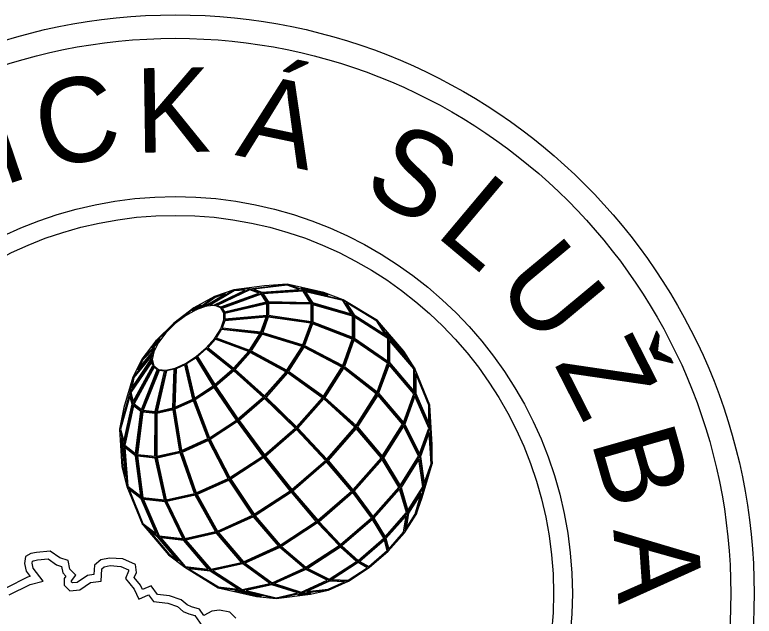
# Model space of a CAD drawing. Extents: x -820854 to -820609, y -1070840 to -1070004.
# Drawn here: x -820678.53 to -820668.06, y -1070178.74 to -1070170.22 of the extents above; entities that cross this region are included whole.
import ezdxf

# ---------------------------------------------------------------- set-up
doc = ezdxf.new("R2010")
doc.units = 0
doc.layers.add('Vrstva 63', color=7, linetype='Continuous')

msp = doc.modelspace()

# ---------------------------------------------------------------- linework, layer by layer
at = {"layer": 'Vrstva 63'}
for p, q in [((-820675.957, -1070174.397), (-820675.698, -1070174.211)), ((-820675.815, -1070174.348), (-820675.426, -1070174.117)), ((-820676.109, -1070174.481), (-820675.99, -1070174.372)), ((-820676.257, -1070174.593), (-820676.275, -1070174.587)), ((-820676.389, -1070174.723), (-820676.528, -1070174.837)), ((-820676.493, -1070174.86), (-820676.727, -1070175.099)), ((-820676.559, -1070174.991), (-820676.854, -1070175.351)), ((-820672.629, -1070176.309), (-820672.664, -1070175.749))]:
    msp.add_line(p, q, dxfattribs=at)
for points in [[(-820676.528, -1070174.837), (-820676.727, -1070175.099), (-820676.854, -1070175.351), (-820676.984, -1070175.784), (-820677.045, -1070176.089), (-820677.013, -1070176.624), (-820676.94, -1070176.902), (-820676.723, -1070177.432), (-820676.353, -1070177.867), (-820676.121, -1070178.046), (-820675.646, -1070178.336), (-820675.104, -1070178.459), (-820674.826, -1070178.49), (-820674.34, -1070178.425), (-820674.087, -1070178.369), (-820673.802, -1070178.24), (-820673.51, -1070178.05), (-820673.238, -1070177.815), (-820673.01, -1070177.556), (-820672.845, -1070177.296), (-820672.759, -1070177.059), (-820672.615, -1070176.58), (-820672.615, -1070176.309), (-820672.651, -1070175.748), (-820672.862, -1070175.23), (-820673.02, -1070174.986), (-820673.39, -1070174.551), (-820673.876, -1070174.255), (-820674.153, -1070174.152), (-820674.669, -1070174.036), (-820674.989, -1070174.06), (-820675.426, -1070174.117), (-820675.698, -1070174.211), (-820675.99, -1070174.372), (-820676.275, -1070174.587)], [(-820675.141, -1070174.107), (-820675.031, -1070174.147), (-820674.502, -1070174.112), (-820674.671, -1070174.05)], [(-820674.475, -1070174.093), (-820674.435, -1070174.108), (-820674.088, -1070174.191), (-820674.157, -1070174.165)], [(-820675.876, -1070174.355), (-820675.82, -1070174.336), (-820675.544, -1070174.172), (-820675.692, -1070174.223)], [(-820675.759, -1070174.331), (-820675.699, -1070174.326), (-820675.267, -1070174.119), (-820675.422, -1070174.13)], [(-820675.197, -1070174.114), (-820675.662, -1070174.337), (-820675.61, -1070174.357), (-820675.072, -1070174.161)], [(-820675.59, -1070174.377), (-820675.559, -1070174.425), (-820674.968, -1070174.285), (-820675.038, -1070174.177)], [(-820675.01, -1070174.172), (-820674.94, -1070174.281), (-820674.343, -1070174.293), (-820674.446, -1070174.135)], [(-820674.41, -1070174.142), (-820674.31, -1070174.296), (-820673.762, -1070174.456), (-820673.884, -1070174.266)], [(-820674.96, -1070174.311), (-820675.552, -1070174.451), (-820675.552, -1070174.527), (-820674.96, -1070174.476)], [(-820674.934, -1070174.308), (-820674.934, -1070174.476), (-820674.332, -1070174.563), (-820674.332, -1070174.32)], [(-820673.833, -1070174.296), (-820673.722, -1070174.469), (-820673.276, -1070174.751), (-820673.399, -1070174.561)], [(-820676.109, -1070175.157), (-820675.957, -1070175.058), (-820675.815, -1070174.935), (-820675.696, -1070174.8), (-820675.61, -1070174.665), (-820675.565, -1070174.541), (-820675.565, -1070174.44), (-820675.61, -1070174.371), (-820675.696, -1070174.339), (-820675.815, -1070174.348), (-820675.957, -1070174.397), (-820676.109, -1070174.481), (-820676.257, -1070174.593), (-820676.389, -1070174.723), (-820676.493, -1070174.86), (-820676.559, -1070174.991), (-820676.581, -1070175.104), (-820676.559, -1070175.191), (-820676.493, -1070175.242), (-820676.389, -1070175.253), (-820676.257, -1070175.224)], [(-820675.982, -1070174.383), (-820676.017, -1070174.415), (-820675.964, -1070174.386), (-820675.888, -1070174.331)], [(-820674.305, -1070174.325), (-820674.305, -1070174.569), (-820673.744, -1070174.786), (-820673.744, -1070174.489)], [(-820674.966, -1070174.503), (-820675.555, -1070174.554), (-820675.592, -1070174.653), (-820675.042, -1070174.711)], [(-820674.337, -1070174.589), (-820674.938, -1070174.502), (-820675.016, -1070174.717), (-820674.447, -1070174.893)], [(-820673.718, -1070174.503), (-820673.718, -1070174.798), (-820673.245, -1070175.124), (-820673.245, -1070174.802)], [(-820676.288, -1070174.619), (-820676.313, -1070174.644)], [(-820676.258, -1070174.592), (-820676.246, -1070174.583)], [(-820673.748, -1070174.813), (-820674.311, -1070174.595), (-820674.423, -1070174.903), (-820673.883, -1070175.185)], [(-820675.056, -1070174.736), (-820675.603, -1070174.679), (-820675.676, -1070174.793), (-820675.203, -1070174.969)], [(-820673.269, -1070174.714), (-820673.221, -1070174.787), (-820672.983, -1070175.067), (-820673.03, -1070174.994)], [(-820676.589, -1070174.939), (-820676.503, -1070174.851), (-820676.468, -1070174.805), (-820676.518, -1070174.847)], [(-820675.22, -1070174.99), (-820675.692, -1070174.816), (-820675.796, -1070174.933), (-820675.428, -1070175.225)], [(-820674.46, -1070174.917), (-820675.027, -1070174.741), (-820675.179, -1070174.98), (-820674.674, -1070175.255)], [(-820673.248, -1070175.155), (-820673.725, -1070174.826), (-820673.86, -1070175.2), (-820673.396, -1070175.562)], [(-820673.219, -1070174.831), (-820673.219, -1070175.145), (-820672.875, -1070175.549), (-820672.875, -1070175.235)], [(-820676.788, -1070175.249), (-820676.57, -1070174.984), (-820676.543, -1070174.931), (-820676.716, -1070175.107)], [(-820673.895, -1070175.209), (-820674.434, -1070174.927), (-820674.651, -1070175.269), (-820674.157, -1070175.622)], [(-820676.872, -1070175.507), (-820676.594, -1070175.099), (-820676.582, -1070175.04), (-820676.841, -1070175.357)], [(-820675.447, -1070175.244), (-820675.815, -1070174.952), (-820675.939, -1070175.06), (-820675.695, -1070175.458)], [(-820674.69, -1070175.276), (-820675.195, -1070175.001), (-820675.408, -1070175.242), (-820674.99, -1070175.616)], [(-820676.85, -1070175.698), (-820676.573, -1070175.189), (-820676.587, -1070175.136), (-820676.883, -1070175.571)], [(-820675.961, -1070175.076), (-820676.094, -1070175.163), (-820675.981, -1070175.648), (-820675.716, -1070175.475)], [(-820676.733, -1070175.811), (-820676.509, -1070175.246), (-820676.555, -1070175.211), (-820676.837, -1070175.731)], [(-820676.405, -1070175.265), (-820676.484, -1070175.256), (-820676.708, -1070175.821), (-820676.538, -1070175.84)], [(-820676.288, -1070175.788), (-820676.271, -1070175.241), (-820676.378, -1070175.264), (-820676.51, -1070175.837)], [(-820676.118, -1070175.176), (-820676.244, -1070175.233), (-820676.261, -1070175.777), (-820676.005, -1070175.662)], [(-820673.873, -1070175.224), (-820674.136, -1070175.639), (-820673.694, -1070176.039), (-820673.408, -1070175.587)], [(-820673.227, -1070175.176), (-820673.375, -1070175.581), (-820673.024, -1070175.993), (-820672.877, -1070175.587)], [(-820675.009, -1070175.635), (-820675.426, -1070175.261), (-820675.681, -1070175.481), (-820675.367, -1070175.944)], [(-820674.173, -1070175.643), (-820674.667, -1070175.291), (-820674.97, -1070175.634), (-820674.538, -1070176.057)], [(-820672.849, -1070175.298), (-820672.849, -1070175.582), (-820672.664, -1070176.01), (-820672.664, -1070175.751)], [(-820675.388, -1070175.96), (-820675.702, -1070175.497), (-820675.974, -1070175.675), (-820675.77, -1070176.21)], [(-820676.985, -1070176.264), (-820676.867, -1070175.734), (-820676.898, -1070175.619), (-820677.031, -1070176.089)], [(-820674.557, -1070176.076), (-820674.989, -1070175.653), (-820675.351, -1070175.965), (-820674.993, -1070176.453)], [(-820674.152, -1070175.66), (-820674.52, -1070176.076), (-820674.11, -1070176.514), (-820673.71, -1070176.061)], [(-820673.388, -1070175.607), (-820673.675, -1070176.058), (-820673.323, -1070176.472), (-820673.036, -1070176.02)], [(-820672.665, -1070176.075), (-820672.861, -1070175.621), (-820673.005, -1070176.018), (-820672.798, -1070176.44)], [(-820676.817, -1070176.433), (-820676.741, -1070175.838), (-820676.845, -1070175.757), (-820676.97, -1070176.315)], [(-820675.794, -1070176.223), (-820675.997, -1070175.687), (-820676.26, -1070175.806), (-820676.165, -1070176.391)], [(-820676.542, -1070176.473), (-820676.541, -1070175.866), (-820676.715, -1070175.847), (-820676.792, -1070176.446)], [(-820676.286, -1070175.814), (-820676.515, -1070175.865), (-820676.516, -1070176.472), (-820676.19, -1070176.4)], [(-820675.015, -1070176.469), (-820675.372, -1070175.981), (-820675.759, -1070176.234), (-820675.481, -1070176.774)], [(-820674.129, -1070176.533), (-820674.539, -1070176.095), (-820674.977, -1070176.474), (-820674.606, -1070176.945)], [(-820673.692, -1070176.08), (-820674.092, -1070176.534), (-820673.74, -1070176.948), (-820673.339, -1070176.494)], [(-820672.811, -1070176.473), (-820673.021, -1070176.046), (-820673.306, -1070176.495), (-820673.072, -1070176.885)], [(-820672.629, -1070176.578), (-820672.66, -1070176.138), (-820672.782, -1070176.475), (-820672.73, -1070176.856)], [(-820676.964, -1070176.757), (-820676.997, -1070176.323), (-820677.024, -1070176.222), (-820677, -1070176.622)], [(-820675.504, -1070176.786), (-820675.783, -1070176.247), (-820676.159, -1070176.417), (-820675.958, -1070176.992)], [(-820676.744, -1070177.037), (-820676.819, -1070176.465), (-820676.969, -1070176.349), (-820676.927, -1070176.895)], [(-820676.409, -1070177.089), (-820676.54, -1070176.5), (-820676.792, -1070176.473), (-820676.714, -1070177.055)], [(-820675.983, -1070177), (-820676.184, -1070176.426), (-820676.513, -1070176.498), (-820676.382, -1070177.088)], [(-820674.628, -1070176.961), (-820674.999, -1070176.49), (-820675.468, -1070176.797), (-820675.138, -1070177.295)], [(-820672.75, -1070176.908), (-820672.804, -1070176.512), (-820673.058, -1070176.913), (-820672.961, -1070177.242)], [(-820674.111, -1070176.552), (-820674.589, -1070176.966), (-820674.237, -1070177.38), (-820673.758, -1070176.967)], [(-820673.089, -1070176.909), (-820673.323, -1070176.517), (-820673.723, -1070176.969), (-820673.456, -1070177.325)], [(-820675.162, -1070177.307), (-820675.491, -1070176.81), (-820675.947, -1070177.016), (-820675.658, -1070177.532)], [(-820676.524, -1070177.569), (-820676.737, -1070177.075), (-820676.909, -1070176.943), (-820676.713, -1070177.423)], [(-820675.684, -1070177.54), (-820675.972, -1070177.025), (-820676.372, -1070177.113), (-820676.12, -1070177.636)], [(-820674.258, -1070177.396), (-820674.611, -1070176.982), (-820675.122, -1070177.316), (-820674.769, -1070177.73)], [(-820673.475, -1070177.344), (-820673.742, -1070176.988), (-820674.219, -1070177.4), (-820673.914, -1070177.723)], [(-820672.981, -1070177.271), (-820673.079, -1070176.937), (-820673.441, -1070177.348), (-820673.283, -1070177.614)], [(-820672.857, -1070177.291), (-820672.773, -1070176.995), (-820672.953, -1070177.279), (-820672.987, -1070177.495)], [(-820676.15, -1070177.636), (-820676.4, -1070177.116), (-820676.705, -1070177.083), (-820676.482, -1070177.599)], [(-820674.793, -1070177.743), (-820675.146, -1070177.329), (-820675.642, -1070177.554), (-820675.29, -1070177.968)], [(-820672.986, -1070177.317), (-820673.271, -1070177.639), (-820673.232, -1070177.787), (-820673.022, -1070177.55)], [(-820673.936, -1070177.739), (-820674.24, -1070177.416), (-820674.75, -1070177.749), (-820674.405, -1070178.046)], [(-820673.303, -1070177.633), (-820673.461, -1070177.367), (-820673.895, -1070177.742), (-820673.666, -1070177.947)], [(-820676.214, -1070177.958), (-820676.5, -1070177.621), (-820676.631, -1070177.52), (-820676.344, -1070177.857)], [(-820675.789, -1070178.07), (-820676.134, -1070177.664), (-820676.459, -1070177.628), (-820676.114, -1070178.033)], [(-820675.318, -1070177.976), (-820675.669, -1070177.564), (-820676.103, -1070177.66), (-820675.752, -1070178.072)], [(-820673.253, -1070177.81), (-820673.293, -1070177.66), (-820673.643, -1070177.962), (-820673.512, -1070178.034)], [(-820674.43, -1070178.059), (-820674.774, -1070177.763), (-820675.267, -1070177.987), (-820674.884, -1070178.264)], [(-820673.688, -1070177.963), (-820673.916, -1070177.759), (-820674.379, -1070178.061), (-820674.074, -1070178.216)], [(-820673.536, -1070178.051), (-820673.665, -1070177.98), (-820674.031, -1070178.219), (-820673.806, -1070178.227)], [(-820675.366, -1070178.354), (-820675.762, -1070178.099), (-820676.063, -1070178.066), (-820675.641, -1070178.324)], [(-820674.917, -1070178.273), (-820675.296, -1070177.998), (-820675.723, -1070178.093), (-820675.309, -1070178.359)], [(-820674.104, -1070178.23), (-820674.406, -1070178.077), (-820674.848, -1070178.277), (-820674.473, -1070178.397)], [(-820674.523, -1070178.409), (-820674.886, -1070178.293), (-820675.252, -1070178.374), (-820674.826, -1070178.476)], [(-820673.859, -1070178.252), (-820674.071, -1070178.244), (-820674.39, -1070178.389), (-820674.09, -1070178.356)], [(-820675.036, -1070178.453), (-820675.313, -1070178.387), (-820675.411, -1070178.376), (-820675.102, -1070178.446)], [(-820674.329, -1070178.409), (-820674.47, -1070178.425), (-820674.52, -1070178.436), (-820674.342, -1070178.412)]]:
    msp.add_lwpolyline(points, close=True, dxfattribs=at)
for points in [[(-820677.045, -1070176.089), (-820676.984, -1070176.32), (-820676.807, -1070176.457), (-820676.529, -1070176.488), (-820676.175, -1070176.41), (-820675.777, -1070176.23), (-820675.369, -1070175.963), (-820674.989, -1070175.635), (-820674.669, -1070175.273), (-820674.439, -1070174.91), (-820674.319, -1070174.578), (-820674.319, -1070174.307), (-820674.439, -1070174.121), (-820674.669, -1070174.036)], [(-820676.854, -1070175.351), (-820676.897, -1070175.569), (-820676.854, -1070175.734), (-820676.727, -1070175.832), (-820676.528, -1070175.854), (-820676.275, -1070175.798), (-820675.99, -1070175.669), (-820675.698, -1070175.479), (-820675.426, -1070175.244), (-820675.198, -1070174.985), (-820675.033, -1070174.725), (-820674.947, -1070174.488), (-820674.947, -1070174.294), (-820675.033, -1070174.161), (-820675.198, -1070174.1), (-820675.426, -1070174.117)], [(-820675.696, -1070174.339), (-820675.198, -1070174.1), (-820674.669, -1070174.036)], [(-820675.61, -1070174.371), (-820675.033, -1070174.161), (-820674.439, -1070174.121), (-820673.876, -1070174.255)], [(-820676.94, -1070176.902), (-820676.726, -1070177.067), (-820676.392, -1070177.104), (-820675.966, -1070177.01), (-820675.486, -1070176.793), (-820674.996, -1070176.472), (-820674.538, -1070176.077), (-820674.153, -1070175.641), (-820673.876, -1070175.204), (-820673.731, -1070174.805), (-820673.731, -1070174.479), (-820673.876, -1070174.255)], [(-820675.565, -1070174.44), (-820674.947, -1070174.294), (-820674.319, -1070174.307), (-820673.731, -1070174.479), (-820673.232, -1070174.795), (-820672.862, -1070175.23)], [(-820675.565, -1070174.541), (-820674.947, -1070174.488), (-820674.319, -1070174.578), (-820673.731, -1070174.805), (-820673.232, -1070175.15), (-820672.862, -1070175.585), (-820672.651, -1070176.075), (-820672.615, -1070176.58)], [(-820676.723, -1070177.432), (-820676.491, -1070177.611), (-820676.127, -1070177.651), (-820675.664, -1070177.549), (-820675.142, -1070177.313), (-820674.608, -1070176.964), (-820674.11, -1070176.534), (-820673.691, -1070176.06), (-820673.39, -1070175.584), (-820673.232, -1070175.15), (-820673.232, -1070174.795), (-820673.39, -1070174.551)], [(-820675.61, -1070174.665), (-820675.033, -1070174.725), (-820674.439, -1070174.91), (-820673.876, -1070175.204), (-820673.39, -1070175.584), (-820673.02, -1070176.019), (-820672.796, -1070176.474), (-820672.736, -1070176.911), (-820672.845, -1070177.296)], [(-820675.696, -1070174.8), (-820675.198, -1070174.985), (-820674.669, -1070175.273), (-820674.153, -1070175.641), (-820673.691, -1070176.06), (-820673.321, -1070176.494), (-820673.073, -1070176.911), (-820672.966, -1070177.274), (-820673.01, -1070177.556)], [(-820675.815, -1070174.935), (-820675.426, -1070175.244), (-820674.989, -1070175.635), (-820674.538, -1070176.077), (-820674.11, -1070176.534), (-820673.74, -1070176.968), (-820673.457, -1070177.346), (-820673.285, -1070177.636), (-820673.238, -1070177.815)], [(-820676.581, -1070175.104), (-820676.897, -1070175.569), (-820677.045, -1070176.089)], [(-820675.957, -1070175.058), (-820675.698, -1070175.479), (-820675.369, -1070175.963), (-820674.996, -1070176.472), (-820674.608, -1070176.964), (-820674.238, -1070177.399), (-820673.915, -1070177.742), (-820673.666, -1070177.965), (-820673.51, -1070178.05)], [(-820676.559, -1070175.191), (-820676.854, -1070175.734), (-820676.984, -1070176.32), (-820676.94, -1070176.902)], [(-820676.493, -1070175.242), (-820676.727, -1070175.832), (-820676.807, -1070176.457), (-820676.726, -1070177.067), (-820676.491, -1070177.611), (-820676.121, -1070178.046)], [(-820676.389, -1070175.253), (-820676.528, -1070175.854), (-820676.529, -1070176.488), (-820676.392, -1070177.104), (-820676.127, -1070177.651), (-820675.757, -1070178.086), (-820675.311, -1070178.374), (-820674.826, -1070178.49)], [(-820676.257, -1070175.224), (-820676.275, -1070175.798), (-820676.175, -1070176.41), (-820675.966, -1070177.01), (-820675.664, -1070177.549), (-820675.294, -1070177.984), (-820674.885, -1070178.279), (-820674.472, -1070178.411), (-820674.087, -1070178.369)], [(-820676.121, -1070178.046), (-820675.757, -1070178.086), (-820675.294, -1070177.984), (-820674.772, -1070177.748), (-820674.238, -1070177.399), (-820673.74, -1070176.968), (-820673.321, -1070176.494), (-820673.02, -1070176.019), (-820672.862, -1070175.585), (-820672.862, -1070175.23)], [(-820676.109, -1070175.157), (-820675.99, -1070175.669), (-820675.777, -1070176.23), (-820675.486, -1070176.793), (-820675.142, -1070177.313), (-820674.772, -1070177.748), (-820674.406, -1070178.062), (-820674.073, -1070178.231), (-820673.802, -1070178.24)], [(-820675.646, -1070178.336), (-820675.311, -1070178.374), (-820674.885, -1070178.279), (-820674.406, -1070178.062), (-820673.915, -1070177.742), (-820673.457, -1070177.346), (-820673.073, -1070176.911), (-820672.796, -1070176.474), (-820672.651, -1070176.075), (-820672.651, -1070175.748)], [(-820674.826, -1070178.49), (-820674.472, -1070178.411), (-820674.073, -1070178.231), (-820673.666, -1070177.965), (-820673.285, -1070177.636), (-820672.966, -1070177.274), (-820672.736, -1070176.911), (-820672.615, -1070176.58)], [(-820678.219, -1070177.837), (-820678.301, -1070177.852), (-820678.375, -1070177.894), (-820678.39, -1070177.992), (-820678.368, -1070178.102), (-820678.31, -1070178.178), (-820678.347, -1070178.187), (-820678.646, -1070178.337)], [(-820675.397, -1070178.767), (-820675.482, -1070178.68), (-820675.629, -1070178.651), (-820675.738, -1070178.665), (-820675.849, -1070178.73), (-820675.913, -1070178.64), (-820676.024, -1070178.605), (-820676.085, -1070178.579), (-820676.169, -1070178.508), (-820676.338, -1070178.45), (-820676.505, -1070178.431), (-820676.597, -1070178.308), (-820676.718, -1070178.359), (-820676.747, -1070178.298), (-820676.837, -1070178.188), (-820676.805, -1070178.118), (-820676.819, -1070178.007), (-820676.998, -1070177.927), (-820677.185, -1070177.914), (-820677.311, -1070177.941), (-820677.397, -1070178.016), (-820677.406, -1070178.148), (-820677.496, -1070178.161), (-820677.646, -1070178.261), (-820677.712, -1070178.268), (-820677.723, -1070178.258), (-820677.722, -1070178.239), (-820677.662, -1070178.159), (-820677.75, -1070178.072), (-820677.772, -1070177.95), (-820677.89, -1070177.913), (-820678.025, -1070177.819), (-820678.219, -1070177.837)], [(-820678.607, -1070178.437), (-820678.31, -1070178.288), (-820678.126, -1070178.244), (-820678.268, -1070178.057), (-820678.282, -1070177.989), (-820678.278, -1070177.961), (-820678.264, -1070177.953), (-820678.205, -1070177.942), (-820678.054, -1070177.928), (-820677.937, -1070178.01), (-820677.865, -1070178.032), (-820677.848, -1070178.124), (-820677.803, -1070178.169), (-820677.828, -1070178.202), (-820677.83, -1070178.301), (-820677.75, -1070178.38), (-820677.608, -1070178.363), (-820677.457, -1070178.262), (-820677.306, -1070178.241), (-820677.294, -1070178.067), (-820677.262, -1070178.039), (-820677.178, -1070178.021), (-820677.024, -1070178.032), (-820676.917, -1070178.08), (-820676.915, -1070178.102), (-820676.961, -1070178.204), (-820676.838, -1070178.355), (-820676.771, -1070178.497), (-820676.633, -1070178.438), (-820676.562, -1070178.532), (-820676.362, -1070178.555), (-820676.222, -1070178.602), (-820676.142, -1070178.67), (-820676.061, -1070178.705), (-820675.979, -1070178.73), (-820675.88, -1070178.871)]]:
    msp.add_lwpolyline(points, dxfattribs=at)
for radius in [8.197, 7.865, 7.865, 5.622, 5.622, 5.356]:
    msp.add_circle((-820676.254, -1070178.416), radius, dxfattribs=at)

# ---------------------------------------------------------------- texts
for s, rotation, p in [('Á', 348.0844, (-820675.418, -1070172.204)), ('K', 0.8492, (-820676.812, -1070172.173)), ('C', 12.7701, (-820678.089, -1070172.422)), ('I', 18.7306, (-820678.702, -1070172.645)), ('S', 331.0575, (-820673.636, -1070172.721)), ('L', 319.9911, (-820672.592, -1070173.329)), ('U', 309.7687, (-820671.747, -1070174.06)), ('Ž', 297.0038, (-820670.896, -1070175.163)), ('B', 285.9374, (-820670.372, -1070176.252)), ('A', 274.0165, (-820670.052, -1070177.514))]:
    msp.add_text(s, height=1.196, rotation=rotation, dxfattribs=at).set_placement(p)

doc.saveas('drawing.dxf')
